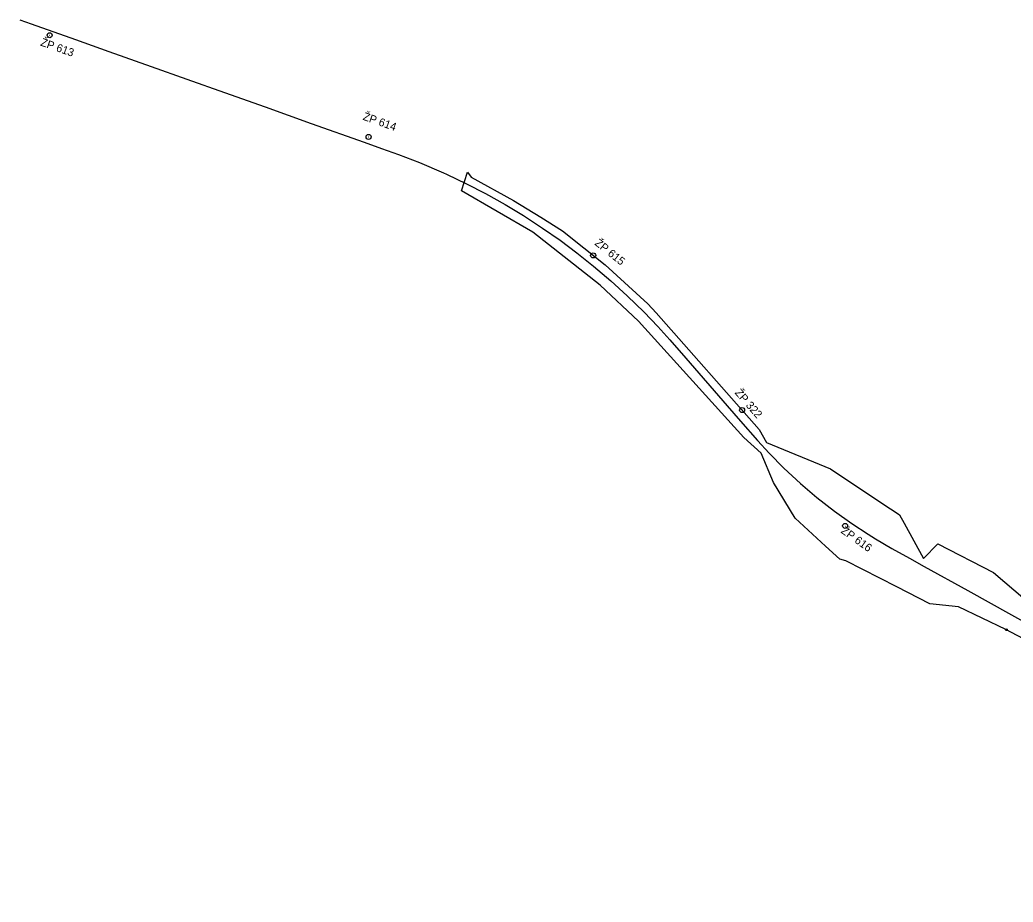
# Model space of a CAD drawing. Extents: x -792643 to -787072, y -1118436 to -1109677.
# Drawn here: x -790535 to -789940, y -1114294 to -1113765 of the extents above; entities that cross this region are included whole.
import ezdxf

# ---------------------------------------------------------------- set-up
doc = ezdxf.new("R2010")
doc.units = 0
for name, color, linetype in [('Vrstva 1', 7, 'Continuous'), ('Vrstva 53', 7, 'Continuous'), ('Vrstva 63', 7, 'Continuous')]:
    doc.layers.add(name, color=color, linetype=linetype)

msp = doc.modelspace()

# ---------------------------------------------------------------- linework, layer by layer
at = {"layer": 'Vrstva 1'}
for points in [[(-790535.44, -1113765.2), (-790528.71, -1113767.58), (-790501.98, -1113777.04), (-790482.05, -1113784.15), (-790456.77, -1113793.15), (-790435.18, -1113800.83), (-790412.68, -1113808.83), (-790388.38, -1113817.43), (-790360.69, -1113827.27), (-790328.86, -1113838.59)], [(-790328.86, -1113838.59), (-790318.45, -1113842.28), (-790308.22, -1113846.01), (-790295.7, -1113850.82), (-790281.35, -1113856.95), (-790279.49, -1113857.79), (-790267.5, -1113863.49), (-790256.07, -1113869.39), (-790244.27, -1113875.99), (-790233.26, -1113882.63), (-790221.86, -1113890.04), (-790211.34, -1113897.39), (-790201.33, -1113904.86), (-790191.22, -1113912.92), (-790180.87, -1113921.77), (-790171.07, -1113930.69), (-790161, -1113940.55), (-790152.67, -1113949.21), (-790145.57, -1113957.06), (-790135.86, -1113968.15)], [(-790135.86, -1113968.15), (-790111.07, -1113996.76), (-790103.1, -1114005.86), (-790092.86, -1114017.53), (-790085.95, -1114025.03), (-790077.08, -1114034.12), (-790067.21, -1114043.25), (-790057.37, -1114051.66), (-790046.83, -1114059.87), (-790036.3, -1114067.37), (-790026.61, -1114073.67), (-790022.09, -1114076.47), (-790012.27, -1114082.22), (-790001.8, -1114088.11), (-789992.89, -1114093.06)], [(-789992.89, -1114093.06), (-789966.79, -1114107.53), (-789928.36, -1114128.84), (-789899.61, -1114144.81), (-789871.25, -1114160.56), (-789840.77, -1114177.49), (-789822.44, -1114187.68), (-789797.27, -1114201.65), (-789768.13, -1114217.82), (-789753.19, -1114226.09), (-789723.93, -1114242.34), (-789718.57, -1114245.31), (-789712.31, -1114248.79)]]:
    msp.add_lwpolyline(points, dxfattribs=at)
at = {"layer": 'Vrstva 53'}
msp.add_line((-789943.63, -1114131.02), (-789943.55, -1114131.07), dxfattribs=at)
for points in [[(-790070.36, -1114064.18), (-790083.26, -1114042.7), (-790090.8, -1114025.12), (-790101.08, -1114015.62), (-790164.37, -1113945.95), (-790187.33, -1113924.36), (-790227.79, -1113892.5), (-790270.49, -1113867.67), (-790266.88, -1113856.5)], [(-790266.88, -1113856.5), (-790264.64, -1113859.59), (-790239.37, -1113873.47), (-790222.82, -1113883.58), (-790209.83, -1113891.74), (-790184.25, -1113912.16), (-790158.65, -1113935.51), (-790153.82, -1113940.85), (-790091.86, -1114010.99), (-790087.54, -1114018.7), (-790049.23, -1114034.44)], [(-790049.23, -1114034.44), (-790014.82, -1114057.41), (-790011.64, -1114059.53), (-790007.66, -1114062.18), (-790004.95, -1114067.14), (-789993.35, -1114088.34), (-789984.83, -1114079.42), (-789951.34, -1114096.74), (-789913.42, -1114129.06), (-789891.43, -1114142.08), (-789830.15, -1114178.38), (-789746.5, -1114225.43), (-789721.98, -1114237.82), (-789717.72, -1114240.35), (-789691.28, -1114256.01), (-789665.23, -1114268.84), (-789640.19, -1114272.7), (-789627.07, -1114282.33), (-789607.19, -1114286.63), (-789603.91, -1114286.39)], [(-789600.46, -1114294.39), (-789619.3, -1114290.36), (-789624.34, -1114291.37), (-789641.23, -1114287.32), (-789672.68, -1114277.31), (-789675.34, -1114276.11), (-789724.61, -1114250.58), (-789730.23, -1114243.59), (-789790.24, -1114210.69), (-789844.34, -1114181.96), (-789891.39, -1114158.73), (-789943.99, -1114130.82), (-789972.38, -1114117.19), (-789989.47, -1114115.38), (-790009.42, -1114105.25), (-790039.99, -1114089.61), (-790043.48, -1114088.64), (-790052.2, -1114080.82), (-790070.36, -1114064.18)]]:
    msp.add_lwpolyline(points, dxfattribs=at)
msp.add_circle((-789943.59, -1114131.04), 0.499, dxfattribs=at)
at = {"layer": 'Vrstva 63'}
for p, q in [((-790517.65, -1113774.36), (-790517.46, -1113774.43)), ((-790326.32, -1113835.38), (-790326.13, -1113835.45)), ((-790191.59, -1113906.39), (-790191.43, -1113906.51)), ((-790102.2, -1113999.17), (-790102.07, -1113999.32)), ((-790040.43, -1114068.64), (-790040.27, -1114068.76))]:
    msp.add_line(p, q, dxfattribs=at)
for centre in [(-790517.56, -1113774.4), (-790326.22, -1113835.42), (-790191.51, -1113906.45), (-790102.14, -1113999.25), (-790040.35, -1114068.7)]:
    msp.add_circle(centre, 1.51, dxfattribs=at)

# ---------------------------------------------------------------- texts
for s, rotation, p in [('ŽP 613', 340.51917, (-790523.48, -1113780.5)), ('ŽP 614', 340.46902, (-790330.07, -1113825.01)), ('ŽP 615', 321.44471, (-790190.99, -1113899.83)), ('ŽP 322', 311.22423, (-790106.85, -1113989.07)), ('ŽP 616', 324.52156, (-790043.27, -1114072.56))]:
    msp.add_text(s, height=4.8, rotation=rotation, dxfattribs=at).set_placement(p)

doc.saveas('drawing.dxf')
